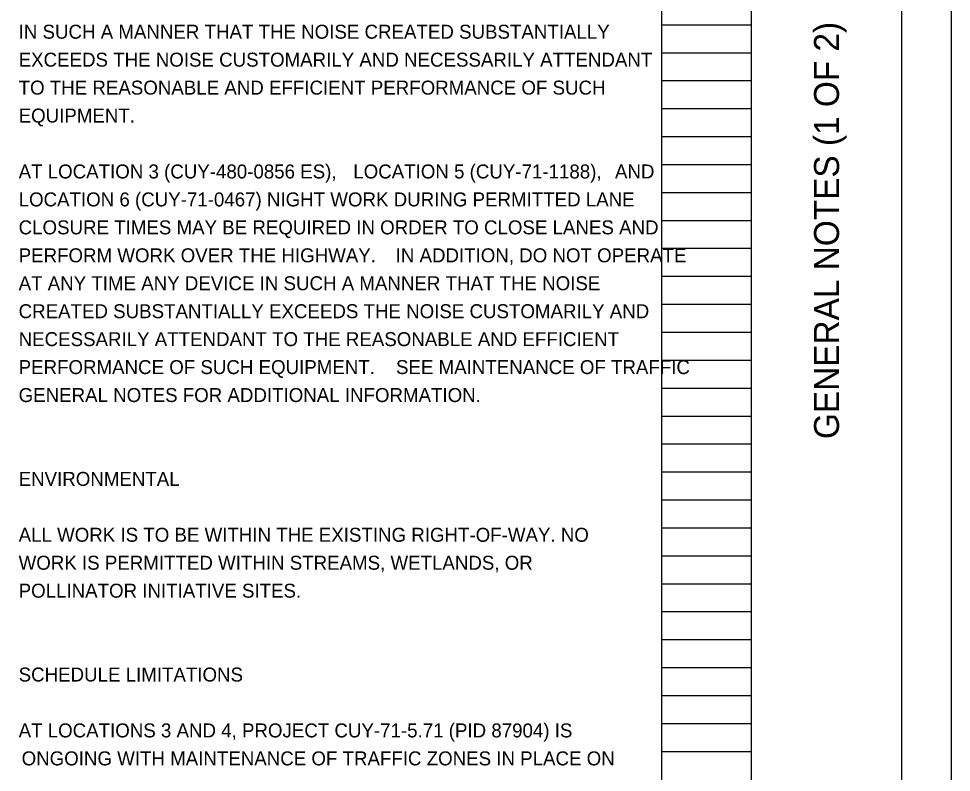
# Model space of a CAD drawing. Extents: x 0 to 34, y -14.6 to 28.2.
# Drawn here: x 24.66 to 34, y 7.49 to 15.04 of the extents above; entities that cross this region are included whole.
import ezdxf

# ---------------------------------------------------------------- set-up
doc = ezdxf.new("R2010")
doc.units = 0
for name, color, linetype in [('SH_Border', 7, 'Continuous'), ('SH_Cut_Line', 7, 'Continuous'), ('SH_Data', 7, 'Continuous'), ('SH_Text', 7, 'Continuous')]:
    doc.layers.add(name, color=color, linetype=linetype)

msp = doc.modelspace()

# ---------------------------------------------------------------- linework, layer by layer
at = {"layer": 'SH_Border'}
msp.add_line((32, 0.5), (32, 21.5), dxfattribs=at)
msp.add_lwpolyline([(1.5, 21.5), (33.5, 21.5), (33.5, 0.5), (1.5, 0.5)], close=True, dxfattribs=at)
at = {"layer": 'SH_Cut_Line'}
msp.add_lwpolyline([(0, 0), (34, 0), (34, 22), (0, 22)], close=True, dxfattribs=at)
at = {"layer": 'SH_Data'}
for p, q in [((31.1, 0.98), (31.1, 21.14)), ((32, 0.98), (32, 21.14)), ((31.1, 14.98), (32, 14.98)), ((31.1, 14.7), (32, 14.7)), ((31.1, 14.42), (32, 14.42)), ((31.1, 14.14), (32, 14.14)), ((31.1, 13.86), (32, 13.86)), ((31.1, 13.58), (32, 13.58)), ((31.1, 13.3), (32, 13.3)), ((31.1, 13.02), (32, 13.02)), ((31.1, 12.74), (32, 12.74)), ((31.1, 12.46), (32, 12.46)), ((31.1, 12.18), (32, 12.18)), ((31.1, 11.9), (32, 11.9)), ((31.1, 11.62), (32, 11.62)), ((31.1, 11.34), (32, 11.34)), ((31.1, 11.06), (32, 11.06)), ((31.1, 10.78), (32, 10.78)), ((31.1, 10.5), (32, 10.5)), ((31.1, 10.22), (32, 10.22)), ((31.1, 9.94), (32, 9.94)), ((31.1, 9.66), (32, 9.66)), ((31.1, 9.38), (32, 9.38)), ((31.1, 9.1), (32, 9.1)), ((31.1, 8.82), (32, 8.82)), ((31.1, 8.54), (32, 8.54)), ((31.1, 8.26), (32, 8.26)), ((31.1, 7.98), (32, 7.98)), ((31.1, 7.7), (32, 7.7))]:
    msp.add_line(p, q, dxfattribs=at)

# ---------------------------------------------------------------- texts
msp.add_text('GENERAL NOTES (1 OF 2)', height=0.25, rotation=90, dxfattribs=at).set_placement((32.875, 10.8293))
at = {"layer": 'SH_Text'}
for s, p in [('IN SUCH A MANNER THAT THE NOISE CREATED SUBSTANTIALLY ', (24.66, 14.84)), ('EXCEEDS THE NOISE CUSTOMARILY AND NECESSARILY ATTENDANT ', (24.66, 14.56)), ('TO THE REASONABLE AND EFFICIENT PERFORMANCE OF SUCH ', (24.66, 14.28)), ('EQUIPMENT.', (24.66, 14)), ('AT LOCATION 3 (CUY-480-0856 ES), ', (24.66, 13.44)), ('LOCATION 5 (CUY-71-1188),', (28.0111, 13.44)), (' AND ', (30.5796, 13.44)), ('LOCATION 6 (CUY-71-0467) NIGHT WORK DURING PERMITTED LANE ', (24.66, 13.16)), ('CLOSURE TIMES MAY BE REQUIRED IN ORDER TO CLOSE LANES AND ', (24.66, 12.88)), ('PERFORM WORK OVER THE HIGHWAY. ', (24.66, 12.6)), ('IN ADDITION, DO NOT OPERATE ', (28.435, 12.6)), ('AT ANY TIME ANY DEVICE IN SUCH A MANNER THAT THE NOISE ', (24.66, 12.32)), ('CREATED SUBSTANTIALLY EXCEEDS THE NOISE CUSTOMARILY AND ', (24.66, 12.04)), ('NECESSARILY ATTENDANT TO THE REASONABLE AND EFFICIENT ', (24.66, 11.76)), ('PERFORMANCE OF SUCH EQUIPMENT. ', (24.66, 11.48)), ('SEE MAINTENANCE OF TRAFFIC ', (28.4388, 11.48)), ('GENERAL NOTES FOR ADDITIONAL INFORMATION.', (24.66, 11.2)), ('ENVIRONMENTAL', (24.66, 10.36)), ('ALL WORK IS TO BE WITHIN THE EXISTING RIGHT-OF-WAY. NO ', (24.66, 9.8)), ('WORK IS PERMITTED WITHIN STREAMS, WETLANDS, OR ', (24.66, 9.52)), ('POLLINATOR INITIATIVE SITES.', (24.66, 9.24)), ('SCHEDULE LIMITATIONS', (24.66, 8.4)), ('AT LOCATIONS 3 AND 4, PROJECT CUY-71-5.71 (PID 87904) IS ', (24.66, 7.84)), ('ONGOING WITH MAINTENANCE OF TRAFFIC ZONES IN PLACE ON ', (24.69, 7.56))]:
    msp.add_text(s, height=0.14, dxfattribs=at).set_placement(p)

doc.saveas('drawing.dxf')
